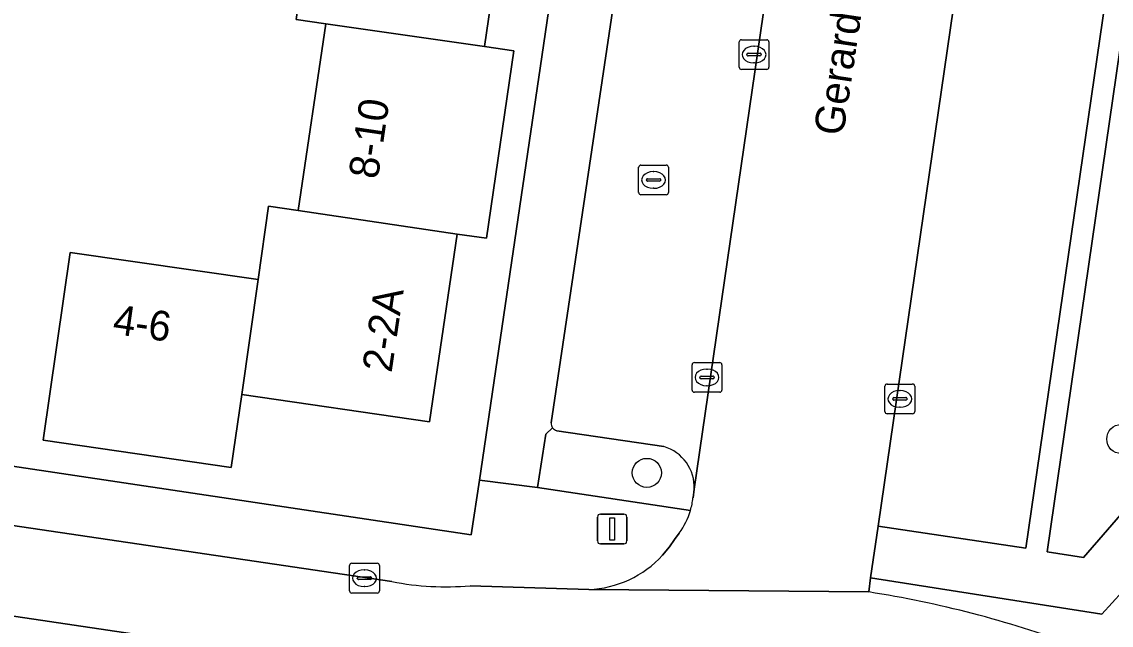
# Model space of a CAD drawing. Extents: x 163683 to 164494, y 382709 to 383872.
# Drawn here: x 163877.1 to 163913.7, y 382945.96 to 382966.23 of the extents above; entities that cross this region are included whole.
import ezdxf

# ---------------------------------------------------------------- set-up
doc = ezdxf.new("R2010")
doc.units = 0
for name, color, linetype in [('IMGEO_Boom', 7, 'Continuous'), ('IMGEO_Brandkraan', 7, 'Continuous'), ('IMGEO_Erf', 7, 'Continuous'), ('IMGEO_Fietspad_gesloten', 7, 'Continuous'), ('IMGEO_Groenvoorziening', 7, 'Continuous'), ('IMGEO_Kolk', 7, 'Continuous'), ('IMGEO_Lichtmast', 7, 'Continuous'), ('IMGEO_Openbare_ruimte_label', 7, 'Continuous'), ('IMGEO_Pand', 7, 'Continuous'), ('IMGEO_Pand_nummerreeks', 7, 'Continuous'), ('IMGEO_Parkeervlak_open', 7, 'Continuous'), ('IMGEO_Rijbaan_lokaal_open', 7, 'Continuous'), ('IMGEO_Verkeerseiland_open', 7, 'Continuous'), ('IMGEO_Voetpad_open', 7, 'Continuous')]:
    doc.layers.add(name, color=color, linetype=linetype)

msp = doc.modelspace()

# ---------------------------------------------------------------- linework, layer by layer
at = {"layer": 'IMGEO_Boom'}
for centre in [(163914.042, 382952.215), (163898.102, 382951.077)]:
    msp.add_circle(centre, 0.489, dxfattribs=at)
at = {"layer": 'IMGEO_Brandkraan'}
for p, q in [((163897.826, 382960.493), (163897.826, 382961.345)), ((163897.901, 382961.419), (163898.753, 382961.419)), ((163898.827, 382961.345), (163898.827, 382960.493)), ((163898.085, 382960.913), (163898.085, 382960.925)), ((163898.523, 382960.876), (163898.125, 382960.876)), ((163898.128, 382960.962), (163898.526, 382960.962)), ((163898.314, 382961.199), (163898.339, 382961.199)), ((163898.569, 382960.925), (163898.569, 382960.913)), ((163898.337, 382960.639), (163898.312, 382960.639)), ((163898.753, 382960.419), (163897.901, 382960.419))]:
    msp.add_line(p, q, dxfattribs=at)
for points in [[(163897.826, 382960.493), (163897.826, 382961.345)], [(163897.901, 382961.419), (163898.753, 382961.419)], [(163898.827, 382961.345), (163898.827, 382960.493)], [(163898.753, 382960.419), (163897.901, 382960.419)]]:
    msp.add_lwpolyline(points, dxfattribs=at)
for centre, radius, start, end in [((163897.903, 382961.343), 0.0765, 91.552, 178.448), ((163897.903, 382961.343), 0.0765, 91.552, 178.448), ((163898.751, 382961.343), 0.0765, 1.552, 88.448), ((163898.751, 382961.343), 0.0765, 1.552, 88.448), ((163898.125, 382960.922), 0.0403, 85.8775, 175.7526), ((163898.122, 382960.912), 0.0366, 178.938, 274.7102), ((163898.526, 382960.919), 0.043, 264.8664, 352.4533), ((163898.53, 382960.924), 0.0386, 1.7309, 96.639), ((163897.903, 382960.495), 0.0765, 181.552, 268.448), ((163897.903, 382960.495), 0.0765, 181.552, 268.448), ((163898.751, 382960.495), 0.0765, 271.552, 358.448), ((163898.751, 382960.495), 0.0765, 271.552, 358.448)]:
    msp.add_arc(centre, radius, start, end, dxfattribs=at)
for centre, major_axis, ratio, start_param, end_param in [((163898.313, 382960.919), (-0.387, 0.002), 0.722429, 4.712389, 7.853982), ((163898.338, 382960.919), (-0.39, 0.002), 0.717154, 1.570796, 4.712389)]:
    msp.add_ellipse(centre, major_axis=major_axis, ratio=ratio, start_param=start_param, end_param=end_param, dxfattribs=at)
at = {"layer": 'IMGEO_Erf'}
for points in [[(163895.924, 382974.275), (163874.081, 382977.44), (163872.816, 382977.623), (163849.405, 382981.015), (163845.732, 382955.951), (163892.203, 382948.993), (163892.473, 382950.83)], [(163887.255, 382972.624), (163893.567, 382971.692), (163892.645, 382965.408), (163893.633, 382965.258), (163892.716, 382958.963), (163891.727, 382959.1), (163890.8, 382952.798), (163884.492, 382953.713), (163884.136, 382951.26), (163877.822, 382952.176), (163878.724, 382958.479), (163885.042, 382957.575), (163885.394, 382960.033), (163886.383, 382959.891), (163887.312, 382966.167), (163886.323, 382966.313)]]:
    msp.add_lwpolyline(points, close=True, dxfattribs=at)
at = {"layer": 'IMGEO_Fietspad_gesloten'}
for points in [[(163889.537, 382947.425), (163848.504, 382953.484), (163841.466, 382955.031), (163836.819, 382955.733), (163829.321, 382956.326), (163789.89, 382962.121)], [(163789.243, 382959.169), (163828.494, 382953.413), (163832.338, 382953.004), (163834.79, 382952.839), (163842.904, 382951.651), (163844.9, 382951.157), (163848.013, 382950.544), (163885.873, 382944.918), (163888.388, 382944.514)], [(163905.557, 382947.078), (163896.153, 382947.159), (163892.166, 382947.287)]]:
    msp.add_lwpolyline(points, dxfattribs=at)
for centre, radius, start, end in [((163891.348, 382956.806), 9.554, 259.0762, 274.9143), ((163899.796, 382910.658), 36.873, 69.9359, 81.0113)]:
    msp.add_arc(centre, radius, start, end, dxfattribs=at)
at = {"layer": 'IMGEO_Groenvoorziening'}
for points in [[(163918.31, 382964.671), (163913.998, 382965.282), (163911.547, 382948.427), (163912.77, 382948.231), (163917.758, 382953.979), (163919.168, 382963.525)], [(163919.234, 382953.124), (163915.475, 382948.612), (163913.391, 382946.329), (163905.621, 382947.552), (163905.557, 382947.078)], [(163894.935, 382952.595), (163894.702, 382952.384), (163894.432, 382950.591), (163899.567, 382949.818)], [(163898.674, 382951.965), (163895.078, 382952.495)], [(163899.652, 382950.24), (163899.694, 382950.529)]]:
    msp.add_lwpolyline(points, dxfattribs=at)
for centre, radius, start, end in [((163895.151, 382952.751), 0.266, 215.901, 254.1688), ((163898.26, 382950.591), 1.435, 357.5352, 73.2377), ((163897.275, 382950.499), 2.391, 343.4468, 353.7767), ((163899.796, 382910.658), 36.873, 69.9359, 81.0113)]:
    msp.add_arc(centre, radius, start, end, dxfattribs=at)
at = {"layer": 'IMGEO_Kolk'}
for p, q in [((163901.279, 382965.631), (163902.131, 382965.631)), ((163901.204, 382964.705), (163901.204, 382965.557)), ((163901.692, 382965.411), (163901.717, 382965.411)), ((163902.205, 382965.557), (163902.205, 382964.705)), ((163901.463, 382965.125), (163901.463, 382965.137)), ((163901.901, 382965.088), (163901.503, 382965.088)), ((163901.506, 382965.174), (163901.904, 382965.174)), ((163901.947, 382965.137), (163901.947, 382965.125)), ((163902.131, 382964.631), (163901.279, 382964.631)), ((163901.715, 382964.851), (163901.69, 382964.851)), ((163899.622, 382953.859), (163899.622, 382954.711)), ((163899.697, 382954.785), (163900.549, 382954.785)), ((163900.623, 382954.711), (163900.623, 382953.859)), ((163899.881, 382954.279), (163899.881, 382954.291)), ((163899.924, 382954.328), (163900.322, 382954.328)), ((163900.11, 382954.565), (163900.135, 382954.565)), ((163900.365, 382954.291), (163900.365, 382954.279)), ((163900.319, 382954.242), (163899.921, 382954.242)), ((163900.133, 382954.005), (163900.108, 382954.005)), ((163906.102, 382953.138), (163906.102, 382953.99)), ((163906.177, 382954.064), (163907.029, 382954.064)), ((163907.103, 382953.99), (163907.103, 382953.138)), ((163900.549, 382953.785), (163899.697, 382953.785)), ((163906.361, 382953.558), (163906.361, 382953.57)), ((163906.799, 382953.521), (163906.401, 382953.521)), ((163906.404, 382953.607), (163906.802, 382953.607)), ((163906.59, 382953.844), (163906.615, 382953.844)), ((163906.845, 382953.57), (163906.845, 382953.558)), ((163906.613, 382953.284), (163906.588, 382953.284)), ((163907.029, 382953.064), (163906.177, 382953.064)), ((163888.189, 382948.04), (163889.041, 382948.04)), ((163888.114, 382947.114), (163888.114, 382947.966)), ((163888.602, 382947.82), (163888.627, 382947.82)), ((163889.115, 382947.966), (163889.115, 382947.114)), ((163888.373, 382947.534), (163888.373, 382947.546)), ((163888.811, 382947.497), (163888.413, 382947.497)), ((163888.416, 382947.583), (163888.814, 382947.583)), ((163888.857, 382947.546), (163888.857, 382947.534)), ((163889.041, 382947.04), (163888.189, 382947.04)), ((163888.625, 382947.26), (163888.6, 382947.26))]:
    msp.add_line(p, q, dxfattribs=at)
for points in [[(163901.279, 382965.631), (163902.131, 382965.631)], [(163901.204, 382964.705), (163901.204, 382965.557)], [(163902.205, 382965.557), (163902.205, 382964.705)], [(163902.131, 382964.631), (163901.279, 382964.631)], [(163899.622, 382953.859), (163899.622, 382954.711)], [(163899.697, 382954.785), (163900.549, 382954.785)], [(163900.623, 382954.711), (163900.623, 382953.859)], [(163906.102, 382953.138), (163906.102, 382953.99)], [(163906.177, 382954.064), (163907.029, 382954.064)], [(163907.103, 382953.99), (163907.103, 382953.138)], [(163900.549, 382953.785), (163899.697, 382953.785)], [(163907.029, 382953.064), (163906.177, 382953.064)], [(163888.189, 382948.04), (163889.041, 382948.04)], [(163888.114, 382947.114), (163888.114, 382947.966)], [(163889.115, 382947.966), (163889.115, 382947.114)], [(163889.041, 382947.04), (163888.189, 382947.04)]]:
    msp.add_lwpolyline(points, dxfattribs=at)
for centre, radius, start, end in [((163901.281, 382965.555), 0.0765, 91.552, 178.448), ((163901.281, 382965.555), 0.0765, 91.552, 178.448), ((163902.129, 382965.555), 0.0765, 1.552, 88.448), ((163902.129, 382965.555), 0.0765, 1.552, 88.448), ((163901.503, 382965.134), 0.0403, 85.8775, 175.7526), ((163901.5, 382965.124), 0.0366, 178.938, 274.7102), ((163901.904, 382965.131), 0.043, 264.8664, 352.4533), ((163901.908, 382965.136), 0.0386, 1.7309, 96.639), ((163901.281, 382964.707), 0.0765, 181.552, 268.448), ((163901.281, 382964.707), 0.0765, 181.552, 268.448), ((163902.129, 382964.707), 0.0765, 271.552, 358.448), ((163902.129, 382964.707), 0.0765, 271.552, 358.448), ((163899.699, 382954.709), 0.0765, 91.552, 178.448), ((163899.699, 382954.709), 0.0765, 91.552, 178.448), ((163900.547, 382954.709), 0.0765, 1.552, 88.448), ((163900.547, 382954.709), 0.0765, 1.552, 88.448), ((163899.921, 382954.288), 0.0403, 85.8775, 175.7526), ((163899.918, 382954.278), 0.0366, 178.938, 274.7102), ((163900.322, 382954.285), 0.043, 264.8664, 352.4533), ((163900.326, 382954.29), 0.0386, 1.7309, 96.639), ((163906.179, 382953.988), 0.0765, 91.552, 178.448), ((163906.179, 382953.988), 0.0765, 91.552, 178.448), ((163907.027, 382953.988), 0.0765, 1.552, 88.448), ((163907.027, 382953.988), 0.0765, 1.552, 88.448), ((163899.699, 382953.861), 0.0765, 181.552, 268.448), ((163899.699, 382953.861), 0.0765, 181.552, 268.448), ((163900.547, 382953.861), 0.0765, 271.552, 358.448), ((163900.547, 382953.861), 0.0765, 271.552, 358.448), ((163906.401, 382953.567), 0.0403, 85.8775, 175.7526), ((163906.398, 382953.557), 0.0366, 178.938, 274.7102), ((163906.802, 382953.564), 0.043, 264.8664, 352.4533), ((163906.806, 382953.569), 0.0386, 1.7309, 96.639), ((163906.179, 382953.14), 0.0765, 181.552, 268.448), ((163906.179, 382953.14), 0.0765, 181.552, 268.448), ((163907.027, 382953.14), 0.0765, 271.552, 358.448), ((163907.027, 382953.14), 0.0765, 271.552, 358.448), ((163888.191, 382947.964), 0.0765, 91.552, 178.448), ((163888.191, 382947.964), 0.0765, 91.552, 178.448), ((163889.039, 382947.964), 0.0765, 1.552, 88.448), ((163889.039, 382947.964), 0.0765, 1.552, 88.448), ((163888.413, 382947.543), 0.0403, 85.8775, 175.7526), ((163888.41, 382947.533), 0.0366, 178.938, 274.7102), ((163888.814, 382947.54), 0.043, 264.8664, 352.4533), ((163888.818, 382947.545), 0.0386, 1.7309, 96.639), ((163888.191, 382947.116), 0.0765, 181.552, 268.448), ((163888.191, 382947.116), 0.0765, 181.552, 268.448), ((163889.039, 382947.116), 0.0765, 271.552, 358.448), ((163889.039, 382947.116), 0.0765, 271.552, 358.448)]:
    msp.add_arc(centre, radius, start, end, dxfattribs=at)
for centre, major_axis, ratio, start_param, end_param in [((163901.691, 382965.131), (-0.387, 0.002), 0.722429, 4.712389, 7.853982), ((163901.716, 382965.131), (-0.39, 0.002), 0.717154, 1.570796, 4.712389), ((163900.109, 382954.285), (-0.387, 0.002), 0.722429, 4.712389, 7.853982), ((163900.134, 382954.285), (-0.39, 0.002), 0.717154, 1.570796, 4.712389), ((163906.589, 382953.564), (-0.387, 0.002), 0.722429, 4.712389, 7.853982), ((163906.614, 382953.564), (-0.39, 0.002), 0.717154, 1.570796, 4.712389), ((163888.601, 382947.54), (-0.387, 0.002), 0.722429, 4.712389, 7.853982), ((163888.626, 382947.54), (-0.39, 0.002), 0.717154, 1.570796, 4.712389)]:
    msp.add_ellipse(centre, major_axis=major_axis, ratio=ratio, start_param=start_param, end_param=end_param, dxfattribs=at)
at = {"layer": 'IMGEO_Lichtmast'}
for p, q in [((163896.441, 382948.793), (163896.441, 382949.593)), ((163896.441, 382949.593), (163896.441, 382948.793)), ((163896.541, 382949.693), (163897.331, 382949.693)), ((163897.331, 382949.693), (163896.541, 382949.693)), ((163897.431, 382949.593), (163897.431, 382948.793)), ((163897.431, 382948.793), (163897.431, 382949.593)), ((163897.331, 382948.693), (163896.541, 382948.693)), ((163896.541, 382948.693), (163897.331, 382948.693))]:
    msp.add_line(p, q, dxfattribs=at)
msp.add_lwpolyline([(163896.861, 382949.568), (163897.011, 382949.568), (163897.011, 382948.818), (163896.861, 382948.818), (163896.861, 382949.568)], dxfattribs=at)
for centre, start, end in [((163896.541, 382949.593), 90, 180), ((163896.541, 382949.593), 90, 180), ((163897.331, 382949.593), 0, 90), ((163897.331, 382949.593), 360, 90), ((163896.541, 382948.793), 180, 270), ((163896.541, 382948.793), 180, 270), ((163897.331, 382948.793), 270, 0), ((163897.331, 382948.793), 270, 0)]:
    msp.add_arc(centre, 0.1, start, end, dxfattribs=at)
at = {"layer": 'IMGEO_Pand'}
for points in [[(163893.567, 382971.692), (163887.255, 382972.624), (163886.323, 382966.313), (163887.312, 382966.167), (163892.645, 382965.408)], [(163893.633, 382965.258), (163892.645, 382965.408), (163887.312, 382966.167), (163886.383, 382959.891), (163891.727, 382959.1), (163892.716, 382958.963)], [(163891.727, 382959.1), (163886.383, 382959.891), (163885.394, 382960.033), (163885.042, 382957.575), (163884.492, 382953.713), (163890.8, 382952.798)], [(163884.492, 382953.713), (163885.042, 382957.575), (163878.724, 382958.479), (163877.822, 382952.176), (163884.136, 382951.26)]]:
    msp.add_lwpolyline(points, close=True, dxfattribs=at)
at = {"layer": 'IMGEO_Parkeervlak_open'}
for points in [[(163909.513, 382974.371), (163905.868, 382949.288), (163910.833, 382948.544), (163914.373, 382972.917), (163911.306, 382973.343), (163910.335, 382973.479)], [(163899.694, 382950.529), (163902.204, 382967.798)], [(163897.067, 382967.43), (163894.887, 382952.759)], [(163895.078, 382952.495), (163898.674, 382951.965)]]:
    msp.add_lwpolyline(points, dxfattribs=at)
for centre, radius, start, end in [((163895.145, 382952.745), 0.258, 176.972, 215.6557), ((163895.151, 382952.751), 0.266, 215.901, 254.1688), ((163898.26, 382950.591), 1.435, 357.5352, 73.2377)]:
    msp.add_arc(centre, radius, start, end, dxfattribs=at)
at = {"layer": 'IMGEO_Rijbaan_lokaal_open'}
for points in [[(163896.153, 382947.159), (163905.557, 382947.078), (163905.621, 382947.552), (163905.868, 382949.288), (163909.513, 382974.371), (163909.629, 382975.079), (163918.053, 383032.612)], [(163904.727, 382985.584), (163902.885, 382972.393), (163902.238, 382968.019), (163902.204, 382967.798), (163899.694, 382950.529), (163899.652, 382950.24)], [(163899.187, 382949.054), (163899.032, 382948.844), (163898.859, 382948.591), (163898.628, 382948.311)]]:
    msp.add_lwpolyline(points, dxfattribs=at)
for centre, radius, start, end in [((163897.275, 382950.499), 2.391, 343.4468, 353.7767), ((163897.198, 382950.52), 2.471, 323.6107, 343.4995), ((163895.998, 382950.727), 3.572, 272.4906, 317.4291)]:
    msp.add_arc(centre, radius, start, end, dxfattribs=at)
at = {"layer": 'IMGEO_Verkeerseiland_open'}
msp.add_lwpolyline([(163847.408, 382949.367), (163885.659, 382943.648), (163885.873, 382944.918), (163848.013, 382950.544), (163844.9, 382951.157), (163842.904, 382951.651), (163834.79, 382952.839), (163832.338, 382953.004), (163828.494, 382953.413), (163789.243, 382959.169)], dxfattribs=at)
at = {"layer": 'IMGEO_Voetpad_open'}
for points in [[(163920.502, 383121.853), (163917.143, 383098.439), (163916.899, 383096.737), (163916.099, 383091.164), (163909.88, 383048.913), (163909.586, 383046.915), (163899.064, 382975.425), (163896.128, 382975.857), (163895.924, 382974.275), (163892.473, 382950.83), (163894.432, 382950.591), (163894.702, 382952.384), (163894.935, 382952.595)], [(163918.613, 382966.436), (163917.615, 382966.583), (163914.866, 382966.987), (163914.267, 382967.075), (163915.074, 382972.819), (163914.373, 382972.917), (163910.833, 382948.544), (163905.868, 382949.288), (163905.621, 382947.552), (163913.391, 382946.329), (163915.475, 382948.612), (163919.234, 382953.124), (163921.14, 382956.617), (163921.462, 382958.804), (163926.828, 382994.736)], [(163894.887, 382952.759), (163897.067, 382967.43)], [(163919.168, 382963.525), (163917.758, 382953.979), (163912.77, 382948.231), (163911.547, 382948.427), (163913.998, 382965.282), (163918.31, 382964.671)], [(163845.732, 382955.951), (163841.534, 382955.938), (163841.466, 382955.031), (163848.504, 382953.484), (163889.537, 382947.425)], [(163899.567, 382949.818), (163894.432, 382950.591), (163892.473, 382950.83), (163892.203, 382948.993), (163845.732, 382955.951)], [(163898.628, 382948.311), (163898.859, 382948.591), (163899.032, 382948.844), (163899.187, 382949.054)], [(163892.166, 382947.287), (163896.153, 382947.159)]]:
    msp.add_lwpolyline(points, dxfattribs=at)
for centre, radius, start, end in [((163895.145, 382952.745), 0.258, 176.972, 215.6557), ((163897.198, 382950.52), 2.471, 323.6107, 343.4995), ((163895.998, 382950.727), 3.572, 272.4906, 317.4291), ((163891.348, 382956.806), 9.554, 259.0762, 274.9143)]:
    msp.add_arc(centre, radius, start, end, dxfattribs=at)

# ---------------------------------------------------------------- texts
at = {"layer": 'IMGEO_Openbare_ruimte_label'}
msp.add_text('Gerard Davidstraat', height=1, rotation=81.4324, dxfattribs=at).set_placement((163904.693, 382962.37))
at = {"layer": 'IMGEO_Pand_nummerreeks'}
for s, rotation, p in [('8-10', 81.5777, (163889.062, 382960.92)), ('2-2A', 81.6293, (163889.523, 382954.422)), ('4-6', 351.8583, (163880.124, 382955.753))]:
    msp.add_text(s, height=1, rotation=rotation, dxfattribs=at).set_placement(p)

doc.saveas('drawing.dxf')
